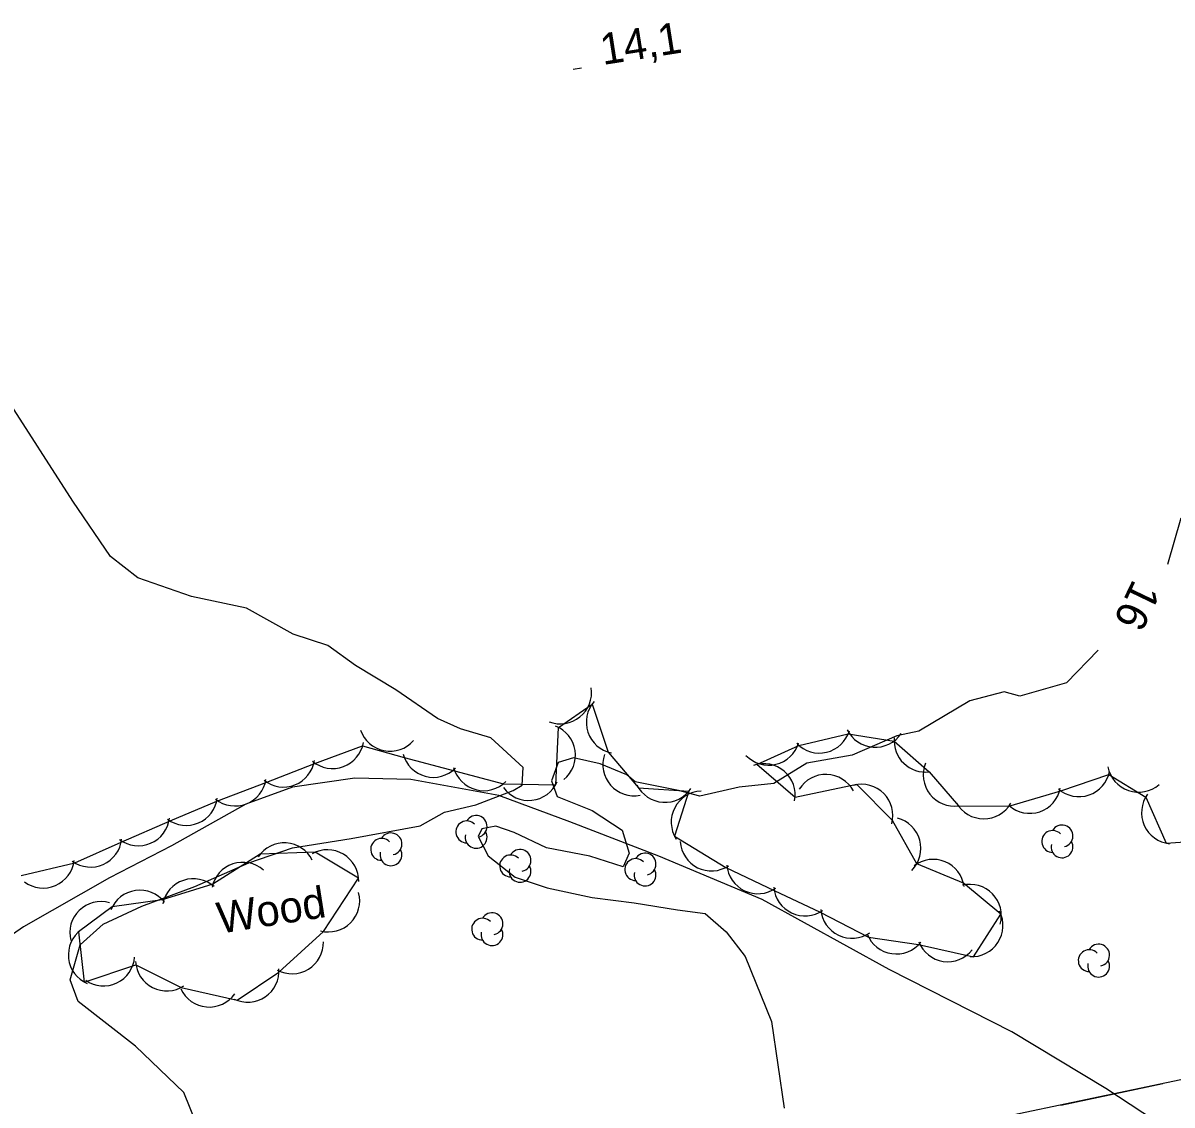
# Model space of a CAD drawing. Extents: x 643342 to 646936, y 5873857 to 5876103.
# Drawn here: x 645941.9 to 646052.2, y 5875826 to 5875930 of the extents above; entities that cross this region are included whole.
import ezdxf

# ---------------------------------------------------------------- set-up
doc = ezdxf.new("R2010")
doc.units = 0
for name, color, linetype in [('Niveau 2', 7, 'Continuous'), ('Niveau 22', 7, 'Continuous'), ('Niveau 3', 7, 'Continuous'), ('Niveau 37', 7, 'Continuous'), ('Niveau 44', 7, 'Continuous')]:
    doc.layers.add(name, color=color, linetype=linetype)

msp = doc.modelspace()

# ---------------------------------------------------------------- linework, layer by layer
at = {"layer": 'Niveau 2'}
for points in [[(645973.79, 5875868.25), (645971.12, 5875870.17), (645967.79, 5875871.27), (645963.31, 5875873.76), (645958.05, 5875874.89), (645952.89, 5875876.67), (645950.27, 5875878.72), (645946.64, 5875884.03), (645940.15, 5875894.15)], [(646053.05, 5875882.4), (646051.74, 5875877.96)], [(646045.11, 5875869.72), (646042.05, 5875866.58), (646037.59, 5875865.29), (646036.08, 5875865.71), (646032.79, 5875864.84), (646027.87, 5875861.93), (646025.76, 5875861.48), (646021.47, 5875859.62), (646017.12, 5875858.87), (646013.96, 5875856.91), (646010.61, 5875856.55), (646006.86, 5875855.69), (646004.81, 5875856.23), (646000.63, 5875857.06), (645999.85, 5875857.74), (645997.28, 5875858.8), (645994.71, 5875859.37), (645993.24, 5875858.93), (645992.62, 5875857.17), (645993.14, 5875855.66), (645996.5, 5875854.33), (645999.4, 5875852.42), (646000.06, 5875850.22), (645999.5, 5875848.89), (645996.29, 5875849.94), (645992.12, 5875850.72), (645989.03, 5875852.2), (645987.27, 5875852.82), (645985.9, 5875852.56), (645985.57, 5875851.83), (645986.54, 5875849.95), (645989.11, 5875847.9), (645992.2, 5875846.89), (645996.51, 5875845.95), (646000.53, 5875845.45), (646004.69, 5875844.78), (646007.36, 5875844.42), (646009.37, 5875842.66), (646011.21, 5875840.29), (646013.73, 5875834.04), (646014.95, 5875825.73)], [(645958.59, 5875824.04), (645957.3, 5875827.22), (645952.65, 5875831.68), (645947.15, 5875835.98), (645946.4, 5875838.06), (645947.36, 5875841.42), (645949.54, 5875843.39), (645953.26, 5875845.13), (645958.36, 5875847.01), (645963.53, 5875849.3), (645967.75, 5875850.74), (645973.37, 5875851.62), (645980.01, 5875852.85), (645982.32, 5875854.14), (645985.33, 5875854.87), (645988.91, 5875856.24), (645989.79, 5875856.74), (645989.89, 5875858.44), (645986.77, 5875861.31), (645983.87, 5875862.16), (645981.66, 5875863.15), (645977.67, 5875865.92), (645973.79, 5875868.25)]]:
    msp.add_lwpolyline(points, dxfattribs=at)
at = {"layer": 'Niveau 22'}
msp.add_lwpolyline([(646061.06, 5875817.6), (646045.82, 5875827.62), (646036.8, 5875833.06), (646025.04, 5875839.03), (646012.85, 5875845.76), (646002.92, 5875849.94), (645994.38, 5875853.22), (645987.56, 5875855.76), (645979.09, 5875857.3), (645973.71, 5875857.43), (645967.74, 5875856.57), (645963.25, 5875854.93), (645956.12, 5875850.91), (645950.15, 5875847.84), (645941.92, 5875843.13), (645935.96, 5875839)], dxfattribs=at)
at = {"layer": 'Niveau 3'}
msp.add_line((645994.69, 5875925.52), (645995.48, 5875925.65), dxfattribs=at)
at = {"layer": 'Niveau 37'}
for points in [[(646156.26, 5875850.21), (646086.41, 5875835.45), (645993.12, 5875815.85), (645903.06, 5875796.81), (645819.6, 5875779.21), (645815.58, 5875797.71), (645725.88, 5875779.09), (645656.81, 5875764.27)], [(646041.52, 5875826.02), (646051.31, 5875828.08)]]:
    msp.add_lwpolyline(points, dxfattribs=at)
at = {"layer": 'Niveau 44'}
for points in [[(645941.67, 5875848.08), (645946.85, 5875849.28), (645951.28, 5875851.27), (645956, 5875853.31), (645960.46, 5875855.21), (645965.26, 5875857.05), (645969.78, 5875858.81), (645974.47, 5875860.53), (645978.47, 5875859.42), (645983.3, 5875858.13), (645987.99, 5875856.89), (645993.01, 5875856.79), (645993.28, 5875862.3), (645996.5, 5875864.53), (645998.05, 5875859.93), (646000.96, 5875856.5), (646005.8, 5875856.18), (646004.42, 5875851.85), (646009.35, 5875848.85), (646014, 5875846.63), (646018.39, 5875844.55), (646023.05, 5875842.14), (646027.86, 5875841.43), (646033.12, 5875840.27), (646035.76, 5875844.35), (646032.17, 5875847.32), (646027.68, 5875849.18), (646025.36, 5875853.35), (646021.93, 5875856.8), (646015.99, 5875855.57), (646012.31, 5875858.74), (646016.37, 5875860.55), (646021.1, 5875861.67), (646025.51, 5875860.97), (646028.86, 5875858.03), (646031.68, 5875854.76), (646036.53, 5875854.74), (646041.52, 5875856.2), (646046.12, 5875857.77), (646049.67, 5875855.61), (646051.64, 5875851.18), (646057.9, 5875851.62)], [(645974.08, 5875847.81), (645969.91, 5875850.31), (645964.64, 5875850.12), (645960.09, 5875847.25), (645955.23, 5875845.73), (645950.43, 5875845.05), (645947.19, 5875842.65), (645947.73, 5875837.83), (645952.7, 5875839.5), (645957.03, 5875837.31), (645962.42, 5875836.08), (645966.43, 5875838.8), (645970.72, 5875842.69), (645974.08, 5875847.81)]]:
    msp.add_lwpolyline(points, dxfattribs=at)
for centre, radius, start, end in [((645993.45, 5875865.64), 3, 248.8357, 8.8136), ((645993.45, 5875865.64), 3, 248.8357, 8.8136), ((645993.45, 5875865.64), 3, 248.8357, 8.8136), ((645998.95, 5875862.79), 3, 138.6155, 258.5934), ((645998.95, 5875862.79), 3, 138.6155, 258.5934), ((645998.95, 5875862.79), 3, 138.6155, 258.5934), ((645991.91, 5875859.63), 3, 308.7165, 68.6945), ((645991.91, 5875859.63), 3, 308.7165, 68.6945), ((645991.91, 5875859.63), 3, 308.7165, 68.6945), ((645977.1, 5875863.01), 3, 198.8, 318.778), ((645977.1, 5875863.01), 3, 198.8, 318.778), ((645977.1, 5875863.01), 3, 198.8, 318.778), ((646018.33, 5875862.83), 3, 223.389, 343.3669), ((646018.33, 5875862.83), 3, 223.389, 343.3669), ((646018.33, 5875862.83), 3, 223.389, 343.3669), ((646023.7, 5875863.39), 3, 205.9412, 325.9192), ((646023.7, 5875863.39), 3, 205.9412, 325.9192), ((646023.7, 5875863.39), 3, 205.9412, 325.9192), ((646028.51, 5875861.01), 3, 174.674, 277.3623), ((646028.51, 5875861.01), 3, 174.674, 277.3623), ((646028.51, 5875861.01), 3, 174.674, 277.3623), ((645971.59, 5875861.35), 3, 230.0912, 350.0692), ((645971.59, 5875861.35), 3, 230.0912, 350.0692), ((645971.59, 5875861.35), 3, 230.0912, 350.0692), ((646013.46, 5875861.67), 3, 223.389, 343.3669), ((646013.46, 5875861.67), 3, 223.389, 343.3669), ((646013.46, 5875861.67), 3, 223.389, 343.3669), ((645966.88, 5875859.57), 3, 231.3625, 351.3405), ((645966.88, 5875859.57), 3, 231.3625, 351.3405), ((645966.88, 5875859.57), 3, 231.3625, 351.3405), ((645981.26, 5875860.5), 3, 195.1378, 315.1157), ((645981.26, 5875860.5), 3, 195.1378, 315.1157), ((645981.26, 5875860.5), 3, 195.1378, 315.1157), ((646000.53, 5875858.73), 3, 161.3765, 281.3544), ((646000.53, 5875858.73), 3, 161.3765, 281.3544), ((646000.53, 5875858.73), 3, 161.3765, 281.3544), ((645986.1, 5875859.22), 3, 195.1378, 315.1157), ((645986.1, 5875859.22), 3, 195.1378, 315.1157), ((645986.1, 5875859.22), 3, 195.1378, 315.1157), ((646013, 5875855.82), 3, 349.2163, 109.1942), ((646013, 5875855.82), 3, 349.2163, 109.1942), ((646013, 5875855.82), 3, 349.2163, 109.1942), ((646031.3, 5875857.73), 3, 158.0039, 277.9818), ((646031.3, 5875857.73), 3, 158.0039, 277.9818), ((646031.3, 5875857.73), 3, 158.0039, 277.9818), ((646043.25, 5875858.65), 3, 228.8675, 348.8454), ((646043.25, 5875858.65), 3, 228.8675, 348.8454), ((646043.25, 5875858.65), 3, 228.8675, 348.8454), ((646048.98, 5875859.08), 3, 190.8622, 310.8401), ((646048.98, 5875859.08), 3, 190.8622, 310.8401), ((646048.98, 5875859.08), 3, 190.8622, 310.8401), ((645962.22, 5875857.75), 3, 231.3625, 351.3405), ((645962.22, 5875857.75), 3, 231.3625, 351.3405), ((645962.22, 5875857.75), 3, 231.3625, 351.3405), ((645990.41, 5875858.28), 3, 216.0773, 336.0552), ((645990.41, 5875858.28), 3, 216.0773, 336.0552), ((645990.41, 5875858.28), 3, 216.0773, 336.0552), ((646003.5, 5875858.1), 3, 206.1883, 326.1663), ((646003.5, 5875858.1), 3, 206.1883, 326.1663), ((646003.5, 5875858.1), 3, 206.1883, 326.1663), ((646018.95, 5875854.79), 3, 28.1987, 148.1767), ((646018.95, 5875854.79), 3, 28.1987, 148.1767), ((646018.95, 5875854.79), 3, 28.1987, 148.1767), ((646022.39, 5875853.83), 3, 344.8584, 104.8363), ((646022.39, 5875853.83), 3, 344.8584, 104.8363), ((646022.39, 5875853.83), 3, 344.8584, 104.8363), ((646007.1, 5875853.19), 3, 92.559, 212.537), ((646007.1, 5875853.19), 3, 92.559, 212.537), ((646007.1, 5875853.19), 3, 92.559, 212.537), ((646038.52, 5875857.04), 3, 228.8675, 348.8454), ((646038.52, 5875857.04), 3, 228.8675, 348.8454), ((646038.52, 5875857.04), 3, 228.8675, 348.8454), ((646052.26, 5875854.11), 3, 144.0024, 263.9803), ((646052.26, 5875854.11), 3, 144.0024, 263.9803), ((646052.26, 5875854.11), 3, 144.0024, 263.9803), ((645957.54, 5875855.88), 3, 233.0233, 353.0012), ((645957.54, 5875855.88), 3, 233.0233, 353.0012), ((645957.54, 5875855.88), 3, 233.0233, 353.0012), ((646034.11, 5875856.52), 3, 209.7591, 329.737), ((646034.11, 5875856.52), 3, 209.7591, 329.737), ((646034.11, 5875856.52), 3, 209.7591, 329.737), ((645952.94, 5875853.93), 3, 233.0233, 353.0012), ((645952.94, 5875853.93), 3, 233.0233, 353.0012), ((645952.94, 5875853.93), 3, 233.0233, 353.0012), ((645985.37, 5875852.79), 1.05, 282.2692, 149.7263), ((646025.07, 5875850.68), 3, 315.2084, 75.1863), ((646025.07, 5875850.68), 3, 315.2084, 75.1863), ((646025.07, 5875850.68), 3, 315.2084, 75.1863), ((645984.47, 5875852.26), 1.05, 44.1154, 269.804), ((646040.73, 5875851.34), 1.05, 44.1154, 269.804), ((646041.63, 5875851.87), 1.05, 282.2692, 149.7263), ((645948.34, 5875851.88), 3, 234.2239, 354.2019), ((645948.34, 5875851.88), 3, 234.2239, 354.2019), ((645948.34, 5875851.88), 3, 234.2239, 354.2019), ((645976.29, 5875850.58), 1.05, 44.1154, 269.804), ((645977.19, 5875851.11), 1.05, 282.2692, 149.7263), ((645985.37, 5875851.74), 1.05, 166.9369, 29.6212), ((646007.96, 5875851.51), 3, 183.594, 303.572), ((646007.96, 5875851.51), 3, 183.594, 303.572), ((646007.96, 5875851.51), 3, 183.594, 303.572), ((646041.63, 5875850.82), 1.05, 166.9369, 29.6212), ((645966.95, 5875848.21), 3, 26.3858, 146.3638), ((645966.95, 5875848.21), 3, 26.3858, 146.3638), ((645966.95, 5875848.21), 3, 26.3858, 146.3638), ((645971.09, 5875847.54), 3, 359.0369, 119.0148), ((645971.09, 5875847.54), 3, 359.0369, 119.0148), ((645971.09, 5875847.54), 3, 359.0369, 119.0148), ((645977.19, 5875850.06), 1.05, 166.9369, 29.6212), ((645989.58, 5875849.52), 1.05, 282.2692, 149.7263), ((646001.59, 5875849.17), 1.05, 282.2692, 149.7263), ((645943.8, 5875849.87), 3, 233.16, 353.1379), ((645943.8, 5875849.87), 3, 233.16, 353.1379), ((645943.8, 5875849.87), 3, 233.16, 353.1379), ((645962.95, 5875846.34), 3, 48.4846, 168.4625), ((645962.95, 5875846.34), 3, 48.4846, 168.4625), ((645962.95, 5875846.34), 3, 48.4846, 168.4625), ((645988.68, 5875848.99), 1.05, 44.1154, 269.804), ((646000.69, 5875848.64), 1.05, 44.1154, 269.804), ((646012.43, 5875849.32), 3, 184.6649, 304.6429), ((646012.43, 5875849.32), 3, 184.6649, 304.6429), ((646012.43, 5875849.32), 3, 184.6649, 304.6429), ((646029.25, 5875846.62), 3, 7.5204, 127.4983), ((646029.25, 5875846.62), 3, 7.5204, 127.4983), ((646029.25, 5875846.62), 3, 7.5204, 127.4983), ((645989.58, 5875848.47), 1.05, 166.9369, 29.6212), ((646001.59, 5875848.12), 1.05, 166.9369, 29.6212), ((645958.21, 5875844.76), 3, 48.4846, 168.4625), ((645958.21, 5875844.76), 3, 48.4846, 168.4625), ((645958.21, 5875844.76), 3, 48.4846, 168.4625), ((646016.95, 5875847.18), 3, 184.6649, 304.6429), ((646016.95, 5875847.18), 3, 184.6649, 304.6429), ((646016.95, 5875847.18), 3, 184.6649, 304.6429), ((646032.8, 5875844.22), 3, 344.1296, 104.1076), ((646032.8, 5875844.22), 3, 344.1296, 104.1076), ((646032.8, 5875844.22), 3, 344.1296, 104.1076), ((645953.08, 5875843.65), 3, 38.0823, 158.0602), ((645953.08, 5875843.65), 3, 38.0823, 158.0602), ((645953.08, 5875843.65), 3, 38.0823, 158.0602), ((645971.19, 5875845.65), 3, 254.9501, 14.928), ((645971.19, 5875845.65), 3, 254.9501, 14.928), ((645971.19, 5875845.65), 3, 254.9501, 14.928), ((645949.35, 5875842.57), 3, 74.3497, 194.3277), ((645949.35, 5875842.57), 3, 74.3497, 194.3277), ((645949.35, 5875842.57), 3, 74.3497, 194.3277), ((646021.46, 5875845.04), 3, 184.6649, 304.6429), ((646021.46, 5875845.04), 3, 184.6649, 304.6429), ((646021.46, 5875845.04), 3, 184.6649, 304.6429), ((646032.96, 5875843.27), 3, 267.0025, 26.9804), ((646032.96, 5875843.27), 3, 267.0025, 26.9804), ((646032.96, 5875843.27), 3, 267.0025, 26.9804), ((645985.99, 5875842.91), 1.05, 44.1154, 269.804), ((645986.89, 5875843.44), 1.05, 282.2692, 149.7263), ((645949.21, 5875840.44), 3, 126.3764, 246.3543), ((645949.21, 5875840.44), 3, 126.3764, 246.3543), ((645949.21, 5875840.44), 3, 126.3764, 246.3543), ((645986.89, 5875842.39), 1.05, 166.9369, 29.6212), ((646025.72, 5875843.53), 3, 201.49, 321.4679), ((646025.72, 5875843.53), 3, 201.49, 321.4679), ((646025.72, 5875843.53), 3, 201.49, 321.4679), ((645967.7, 5875841.63), 3, 241.5412, 1.5191), ((645967.7, 5875841.63), 3, 241.5412, 1.5191), ((645967.7, 5875841.63), 3, 241.5412, 1.5191), ((646030.66, 5875842.79), 3, 201.49, 321.4679), ((646030.66, 5875842.79), 3, 201.49, 321.4679), ((646030.66, 5875842.79), 3, 201.49, 321.4679), ((646045.14, 5875840.42), 1.05, 282.2692, 149.7263), ((645949.59, 5875840.47), 3, 235.2411, 355.219), ((645949.59, 5875840.47), 3, 235.2411, 355.219), ((645949.59, 5875840.47), 3, 235.2411, 355.219), ((646044.24, 5875839.89), 1.05, 44.1154, 269.804), ((645955.66, 5875839.98), 3, 183.1279, 303.1059), ((645955.66, 5875839.98), 3, 183.1279, 303.1059), ((645955.66, 5875839.98), 3, 183.1279, 303.1059), ((645963.44, 5875838.9), 3, 244.1578, 4.1357), ((645963.44, 5875838.9), 3, 244.1578, 4.1357), ((645963.44, 5875838.9), 3, 244.1578, 4.1357), ((646045.14, 5875839.37), 1.05, 166.9369, 29.6212), ((645959.74, 5875838.43), 3, 204.8095, 324.7874), ((645959.74, 5875838.43), 3, 204.8095, 324.7874), ((645959.74, 5875838.43), 3, 204.8095, 324.7874)]:
    msp.add_arc(centre, radius, start, end, dxfattribs=at)

# ---------------------------------------------------------------- texts
at = {"layer": 'Niveau 2'}
msp.add_text('16', height=3, rotation=244.2845, dxfattribs=at).set_placement((646048.48, 5875876.63))
at = {"layer": 'Niveau 3'}
msp.add_text('14,1 ', height=3, rotation=8.9405, dxfattribs=at).set_placement((645997.54, 5875925.93))
at = {"layer": 'Niveau 44'}
msp.add_text('Wood', height=3, rotation=8.9405, dxfattribs=at).set_placement((645960.74, 5875842.47))

doc.saveas('drawing.dxf')
